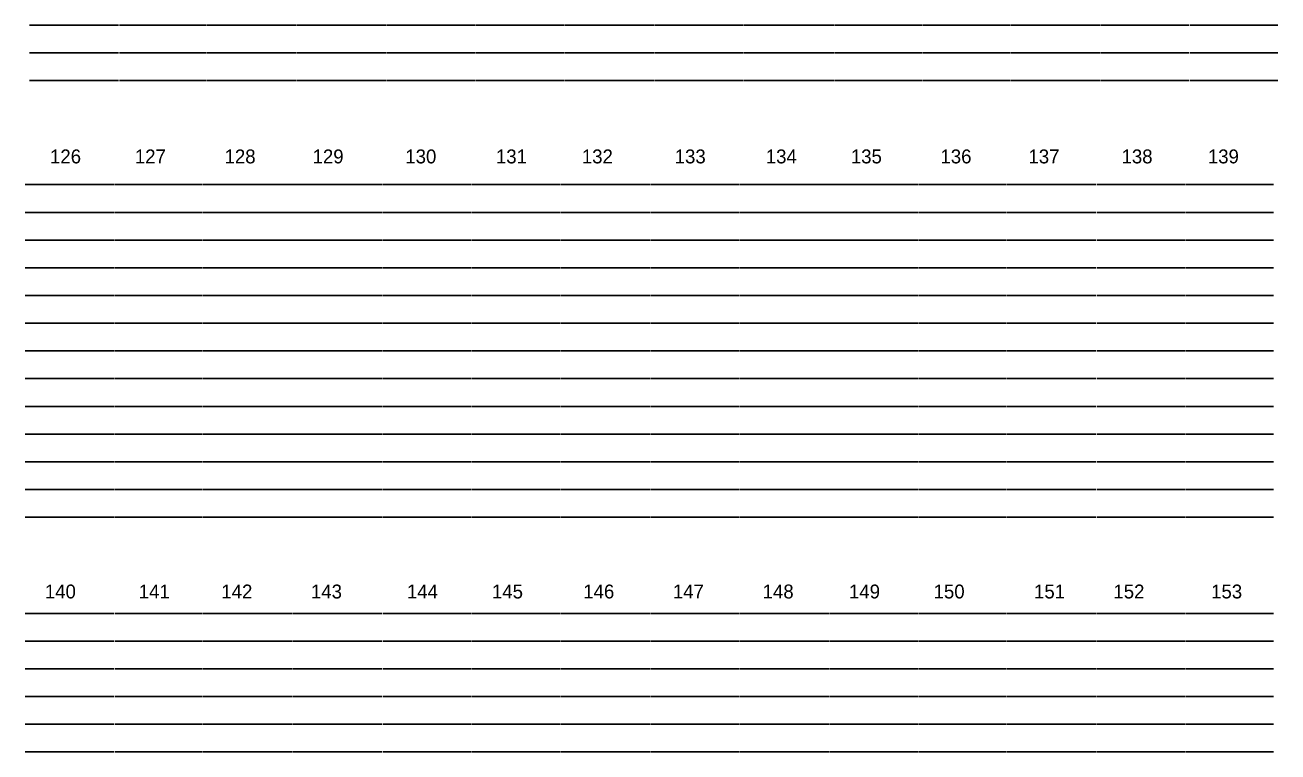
# Model space of a CAD drawing. Extents: x 11193 to 12507, y 10092 to 10555.
# Drawn here: x 11448.5 to 11644.1, y 10324.8 to 10438.4 of the extents above; entities that cross this region are included whole.
import ezdxf

# ---------------------------------------------------------------- set-up
doc = ezdxf.new("R2010")
doc.units = 0
doc.layers.add('Level 2', color=7, linetype='Continuous')

msp = doc.modelspace()

# ---------------------------------------------------------------- linework, layer by layer
at = {"layer": 'Level 2'}
for p, q in [((11449.15, 10438.4), (11463.08, 10438.4)), ((11463.2, 10438.4), (11476.76, 10438.4)), ((11476.87, 10438.4), (11490.84, 10438.4)), ((11490.96, 10438.4), (11504.92, 10438.4)), ((11505.04, 10438.4), (11518.81, 10438.4)), ((11518.92, 10438.4), (11532.69, 10438.4)), ((11532.79, 10438.4), (11546.77, 10438.4)), ((11546.87, 10438.4), (11560.65, 10438.4)), ((11560.75, 10438.4), (11574.74, 10438.4)), ((11574.84, 10438.4), (11588.61, 10438.4)), ((11588.71, 10438.4), (11602.29, 10438.4)), ((11602.39, 10438.4), (11616.37, 10438.4)), ((11616.47, 10438.4), (11630.25, 10438.4)), ((11630.36, 10438.4), (11644.09, 10438.4)), ((11449.15, 10434.07), (11463.08, 10434.07)), ((11463.2, 10434.07), (11476.76, 10434.07)), ((11476.87, 10434.07), (11490.84, 10434.07)), ((11490.96, 10434.07), (11504.92, 10434.07)), ((11505.04, 10434.07), (11518.81, 10434.07)), ((11518.92, 10434.07), (11532.69, 10434.07)), ((11532.79, 10434.07), (11546.77, 10434.07)), ((11546.87, 10434.07), (11560.65, 10434.07)), ((11560.75, 10434.07), (11574.74, 10434.07)), ((11574.84, 10434.07), (11588.61, 10434.07)), ((11588.71, 10434.07), (11602.29, 10434.07)), ((11602.39, 10434.07), (11616.37, 10434.07)), ((11616.47, 10434.07), (11630.25, 10434.07)), ((11630.36, 10434.07), (11644.09, 10434.07)), ((11449.15, 10429.74), (11463.08, 10429.74)), ((11463.2, 10429.74), (11476.76, 10429.74)), ((11476.87, 10429.74), (11490.84, 10429.74)), ((11490.96, 10429.74), (11504.92, 10429.74)), ((11505.04, 10429.74), (11518.81, 10429.74)), ((11518.92, 10429.74), (11532.69, 10429.74)), ((11532.79, 10429.74), (11546.77, 10429.74)), ((11546.87, 10429.74), (11560.65, 10429.74)), ((11560.75, 10429.74), (11574.74, 10429.74)), ((11574.84, 10429.74), (11588.61, 10429.74)), ((11588.71, 10429.74), (11602.29, 10429.74)), ((11602.39, 10429.74), (11616.37, 10429.74)), ((11616.47, 10429.74), (11630.25, 10429.74)), ((11630.36, 10429.74), (11644.09, 10429.74)), ((11448.48, 10413.46), (11462.4, 10413.46)), ((11462.5, 10413.46), (11476.08, 10413.46)), ((11476.18, 10413.46), (11490.16, 10413.46)), ((11490.26, 10413.46), (11504.24, 10413.46)), ((11504.35, 10413.46), (11518.12, 10413.46)), ((11518.23, 10413.46), (11532, 10413.46)), ((11532.11, 10413.46), (11546.08, 10413.46)), ((11546.19, 10413.46), (11559.97, 10413.46)), ((11560.08, 10413.46), (11574.05, 10413.46)), ((11574.15, 10413.46), (11587.93, 10413.46)), ((11588.04, 10413.46), (11601.6, 10413.46)), ((11601.71, 10413.46), (11615.68, 10413.46)), ((11615.79, 10413.46), (11629.57, 10413.46)), ((11629.68, 10413.46), (11643.42, 10413.46)), ((11448.48, 10409.13), (11462.4, 10409.13)), ((11462.5, 10409.13), (11476.08, 10409.13)), ((11476.18, 10409.13), (11490.16, 10409.13)), ((11490.26, 10409.13), (11504.24, 10409.13)), ((11504.35, 10409.13), (11518.12, 10409.13)), ((11518.23, 10409.13), (11532, 10409.13)), ((11532.11, 10409.13), (11546.08, 10409.13)), ((11546.19, 10409.13), (11559.97, 10409.13)), ((11560.08, 10409.13), (11574.05, 10409.13)), ((11574.15, 10409.13), (11587.93, 10409.13)), ((11588.04, 10409.13), (11601.6, 10409.13)), ((11601.71, 10409.13), (11615.68, 10409.13)), ((11615.79, 10409.13), (11629.57, 10409.13)), ((11629.68, 10409.13), (11643.42, 10409.13)), ((11448.48, 10404.8), (11462.4, 10404.8)), ((11462.5, 10404.8), (11476.08, 10404.8)), ((11476.18, 10404.8), (11490.16, 10404.8)), ((11490.26, 10404.8), (11504.24, 10404.8)), ((11504.35, 10404.8), (11518.12, 10404.8)), ((11518.23, 10404.8), (11532, 10404.8)), ((11532.11, 10404.8), (11546.08, 10404.8)), ((11546.19, 10404.8), (11559.97, 10404.8)), ((11560.08, 10404.8), (11574.05, 10404.8)), ((11574.15, 10404.8), (11587.93, 10404.8)), ((11588.04, 10404.8), (11601.6, 10404.8)), ((11601.71, 10404.8), (11615.68, 10404.8)), ((11615.79, 10404.8), (11629.57, 10404.8)), ((11629.68, 10404.8), (11643.42, 10404.8)), ((11448.48, 10400.47), (11462.4, 10400.47)), ((11462.5, 10400.47), (11476.08, 10400.47)), ((11476.18, 10400.47), (11490.16, 10400.47)), ((11490.26, 10400.47), (11504.24, 10400.47)), ((11504.35, 10400.47), (11518.12, 10400.47)), ((11518.23, 10400.47), (11532, 10400.47)), ((11532.11, 10400.47), (11546.08, 10400.47)), ((11546.19, 10400.47), (11559.97, 10400.47)), ((11560.08, 10400.47), (11574.05, 10400.47)), ((11574.15, 10400.47), (11587.93, 10400.47)), ((11588.04, 10400.47), (11601.6, 10400.47)), ((11601.71, 10400.47), (11615.68, 10400.47)), ((11615.79, 10400.47), (11629.57, 10400.47)), ((11629.68, 10400.47), (11643.42, 10400.47)), ((11448.48, 10396.14), (11462.4, 10396.14)), ((11462.5, 10396.14), (11476.08, 10396.14)), ((11476.18, 10396.14), (11490.16, 10396.14)), ((11490.26, 10396.14), (11504.24, 10396.14)), ((11504.35, 10396.14), (11518.12, 10396.14)), ((11518.23, 10396.14), (11532, 10396.14)), ((11532.11, 10396.14), (11546.08, 10396.14)), ((11546.19, 10396.14), (11559.97, 10396.14)), ((11560.08, 10396.14), (11574.05, 10396.14)), ((11574.15, 10396.14), (11587.93, 10396.14)), ((11588.04, 10396.14), (11601.6, 10396.14)), ((11601.71, 10396.14), (11615.68, 10396.14)), ((11615.79, 10396.14), (11629.57, 10396.14)), ((11629.68, 10396.14), (11643.42, 10396.14)), ((11448.48, 10391.8), (11462.4, 10391.8)), ((11462.5, 10391.8), (11476.08, 10391.8)), ((11476.18, 10391.8), (11490.16, 10391.8)), ((11490.26, 10391.8), (11504.24, 10391.8)), ((11504.35, 10391.8), (11518.12, 10391.8)), ((11518.23, 10391.8), (11532, 10391.8)), ((11532.11, 10391.8), (11546.08, 10391.8)), ((11546.19, 10391.8), (11559.97, 10391.8)), ((11560.08, 10391.8), (11574.05, 10391.8)), ((11574.15, 10391.8), (11587.93, 10391.8)), ((11588.04, 10391.8), (11601.6, 10391.8)), ((11601.71, 10391.8), (11615.68, 10391.8)), ((11615.79, 10391.8), (11629.57, 10391.8)), ((11629.68, 10391.8), (11643.42, 10391.8)), ((11448.48, 10387.47), (11462.4, 10387.47)), ((11462.5, 10387.47), (11476.08, 10387.47)), ((11476.18, 10387.47), (11490.16, 10387.47)), ((11490.26, 10387.47), (11504.24, 10387.47)), ((11504.35, 10387.47), (11518.12, 10387.47)), ((11518.23, 10387.47), (11532, 10387.47)), ((11532.11, 10387.47), (11546.08, 10387.47)), ((11546.19, 10387.47), (11559.97, 10387.47)), ((11560.08, 10387.47), (11574.05, 10387.47)), ((11574.15, 10387.47), (11587.93, 10387.47)), ((11588.04, 10387.47), (11601.6, 10387.47)), ((11601.71, 10387.47), (11615.68, 10387.47)), ((11615.79, 10387.47), (11629.57, 10387.47)), ((11629.68, 10387.47), (11643.42, 10387.47)), ((11448.48, 10383.14), (11462.4, 10383.14)), ((11462.5, 10383.14), (11476.08, 10383.14)), ((11476.18, 10383.14), (11490.16, 10383.14)), ((11490.26, 10383.14), (11504.24, 10383.14)), ((11504.35, 10383.14), (11518.12, 10383.14)), ((11518.23, 10383.14), (11532, 10383.14)), ((11532.11, 10383.14), (11546.08, 10383.14)), ((11546.19, 10383.14), (11559.97, 10383.14)), ((11560.08, 10383.14), (11574.05, 10383.14)), ((11574.15, 10383.14), (11587.93, 10383.14)), ((11588.04, 10383.14), (11601.6, 10383.14)), ((11601.71, 10383.14), (11615.68, 10383.14)), ((11615.79, 10383.14), (11629.57, 10383.14)), ((11629.68, 10383.14), (11643.42, 10383.14)), ((11448.48, 10378.81), (11462.4, 10378.81)), ((11462.5, 10378.81), (11476.08, 10378.81)), ((11476.18, 10378.81), (11490.16, 10378.81)), ((11490.26, 10378.81), (11504.24, 10378.81)), ((11504.35, 10378.81), (11518.12, 10378.81)), ((11518.23, 10378.81), (11532, 10378.81)), ((11532.11, 10378.81), (11546.08, 10378.81)), ((11546.19, 10378.81), (11559.97, 10378.81)), ((11560.08, 10378.81), (11574.05, 10378.81)), ((11574.15, 10378.81), (11587.93, 10378.81)), ((11588.04, 10378.81), (11601.6, 10378.81)), ((11601.71, 10378.81), (11615.68, 10378.81)), ((11615.79, 10378.81), (11629.57, 10378.81)), ((11629.68, 10378.81), (11643.42, 10378.81)), ((11448.48, 10374.48), (11462.4, 10374.48)), ((11462.5, 10374.48), (11476.08, 10374.48)), ((11476.18, 10374.48), (11490.16, 10374.48)), ((11490.26, 10374.48), (11504.24, 10374.48)), ((11504.35, 10374.48), (11518.12, 10374.48)), ((11518.23, 10374.48), (11532, 10374.48)), ((11532.11, 10374.48), (11546.08, 10374.48)), ((11546.19, 10374.48), (11559.97, 10374.48)), ((11560.08, 10374.48), (11574.05, 10374.48)), ((11574.15, 10374.48), (11587.93, 10374.48)), ((11588.04, 10374.48), (11601.6, 10374.48)), ((11601.71, 10374.48), (11615.68, 10374.48)), ((11615.79, 10374.48), (11629.57, 10374.48)), ((11629.68, 10374.48), (11643.42, 10374.48)), ((11448.48, 10370.14), (11462.4, 10370.14)), ((11462.5, 10370.14), (11476.08, 10370.14)), ((11476.18, 10370.14), (11490.16, 10370.14)), ((11490.26, 10370.14), (11504.24, 10370.14)), ((11504.35, 10370.14), (11518.12, 10370.14)), ((11518.23, 10370.14), (11532, 10370.14)), ((11532.11, 10370.14), (11546.08, 10370.14)), ((11546.19, 10370.14), (11559.97, 10370.14)), ((11560.08, 10370.14), (11574.05, 10370.14)), ((11574.15, 10370.14), (11587.93, 10370.14)), ((11588.04, 10370.14), (11601.6, 10370.14)), ((11601.71, 10370.14), (11615.68, 10370.14)), ((11615.79, 10370.14), (11629.57, 10370.14)), ((11629.68, 10370.14), (11643.42, 10370.14)), ((11448.48, 10365.81), (11462.4, 10365.81)), ((11462.5, 10365.81), (11476.08, 10365.81)), ((11476.18, 10365.81), (11490.16, 10365.81)), ((11490.26, 10365.81), (11504.24, 10365.81)), ((11504.35, 10365.81), (11518.12, 10365.81)), ((11518.23, 10365.81), (11532, 10365.81)), ((11532.11, 10365.81), (11546.08, 10365.81)), ((11546.19, 10365.81), (11559.97, 10365.81)), ((11560.08, 10365.81), (11574.05, 10365.81)), ((11574.15, 10365.81), (11587.93, 10365.81)), ((11588.04, 10365.81), (11601.6, 10365.81)), ((11601.71, 10365.81), (11615.68, 10365.81)), ((11615.79, 10365.81), (11629.57, 10365.81)), ((11629.68, 10365.81), (11643.42, 10365.81)), ((11448.48, 10361.48), (11462.4, 10361.48)), ((11462.5, 10361.48), (11476.08, 10361.48)), ((11476.18, 10361.48), (11490.16, 10361.48)), ((11490.26, 10361.48), (11504.24, 10361.48)), ((11504.35, 10361.48), (11518.12, 10361.48)), ((11518.23, 10361.48), (11532, 10361.48)), ((11532.11, 10361.48), (11546.08, 10361.48)), ((11546.19, 10361.48), (11559.97, 10361.48)), ((11560.08, 10361.48), (11574.05, 10361.48)), ((11574.15, 10361.48), (11587.93, 10361.48)), ((11588.04, 10361.48), (11601.6, 10361.48)), ((11601.71, 10361.48), (11615.68, 10361.48)), ((11615.79, 10361.48), (11629.57, 10361.48)), ((11629.68, 10361.48), (11643.42, 10361.48)), ((11448.48, 10346.46), (11462.41, 10346.46)), ((11462.53, 10346.46), (11476.09, 10346.46)), ((11476.2, 10346.46), (11490.17, 10346.46)), ((11490.29, 10346.46), (11504.25, 10346.46)), ((11504.37, 10346.46), (11518.14, 10346.46)), ((11518.25, 10346.46), (11532.02, 10346.46)), ((11532.12, 10346.46), (11546.1, 10346.46)), ((11546.2, 10346.46), (11559.98, 10346.46)), ((11560.08, 10346.46), (11574.07, 10346.46)), ((11574.17, 10346.46), (11587.94, 10346.46)), ((11588.04, 10346.46), (11601.62, 10346.46)), ((11601.72, 10346.46), (11615.7, 10346.46)), ((11615.8, 10346.46), (11629.58, 10346.46)), ((11629.69, 10346.46), (11643.42, 10346.46)), ((11448.48, 10342.13), (11462.41, 10342.13)), ((11462.53, 10342.13), (11476.09, 10342.13)), ((11476.2, 10342.13), (11490.17, 10342.13)), ((11490.29, 10342.13), (11504.25, 10342.13)), ((11504.37, 10342.13), (11518.14, 10342.13)), ((11518.25, 10342.13), (11532.02, 10342.13)), ((11532.12, 10342.13), (11546.1, 10342.13)), ((11546.2, 10342.13), (11559.98, 10342.13)), ((11560.08, 10342.13), (11574.07, 10342.13)), ((11574.17, 10342.13), (11587.94, 10342.13)), ((11588.04, 10342.13), (11601.62, 10342.13)), ((11601.72, 10342.13), (11615.7, 10342.13)), ((11615.8, 10342.13), (11629.58, 10342.13)), ((11629.69, 10342.13), (11643.42, 10342.13)), ((11448.48, 10337.79), (11462.41, 10337.79)), ((11462.53, 10337.79), (11476.09, 10337.79)), ((11476.2, 10337.79), (11490.17, 10337.79)), ((11490.29, 10337.79), (11504.25, 10337.79)), ((11504.37, 10337.79), (11518.14, 10337.79)), ((11518.25, 10337.79), (11532.02, 10337.79)), ((11532.12, 10337.79), (11546.1, 10337.79)), ((11546.2, 10337.79), (11559.98, 10337.79)), ((11560.08, 10337.79), (11574.07, 10337.79)), ((11574.17, 10337.79), (11587.94, 10337.79)), ((11588.04, 10337.79), (11601.62, 10337.79)), ((11601.72, 10337.79), (11615.7, 10337.79)), ((11615.8, 10337.79), (11629.58, 10337.79)), ((11629.69, 10337.79), (11643.42, 10337.79)), ((11448.48, 10333.46), (11462.41, 10333.46)), ((11462.53, 10333.46), (11476.09, 10333.46)), ((11476.2, 10333.46), (11490.17, 10333.46)), ((11490.29, 10333.46), (11504.25, 10333.46)), ((11504.37, 10333.46), (11518.14, 10333.46)), ((11518.25, 10333.46), (11532.02, 10333.46)), ((11532.12, 10333.46), (11546.1, 10333.46)), ((11546.2, 10333.46), (11559.98, 10333.46)), ((11560.08, 10333.46), (11574.07, 10333.46)), ((11574.17, 10333.46), (11587.94, 10333.46)), ((11588.04, 10333.46), (11601.62, 10333.46)), ((11601.72, 10333.46), (11615.7, 10333.46)), ((11615.8, 10333.46), (11629.58, 10333.46)), ((11629.69, 10333.46), (11643.42, 10333.46)), ((11448.48, 10329.13), (11462.41, 10329.13)), ((11462.53, 10329.13), (11476.09, 10329.13)), ((11476.2, 10329.13), (11490.17, 10329.13)), ((11490.29, 10329.13), (11504.25, 10329.13)), ((11504.37, 10329.13), (11518.14, 10329.13)), ((11518.25, 10329.13), (11532.02, 10329.13)), ((11532.12, 10329.13), (11546.1, 10329.13)), ((11546.2, 10329.13), (11559.98, 10329.13)), ((11560.08, 10329.13), (11574.07, 10329.13)), ((11574.17, 10329.13), (11587.94, 10329.13)), ((11588.04, 10329.13), (11601.62, 10329.13)), ((11601.72, 10329.13), (11615.7, 10329.13)), ((11615.8, 10329.13), (11629.58, 10329.13)), ((11629.69, 10329.13), (11643.42, 10329.13)), ((11448.48, 10324.8), (11462.41, 10324.8)), ((11462.53, 10324.8), (11476.09, 10324.8)), ((11476.2, 10324.8), (11490.17, 10324.8)), ((11490.29, 10324.8), (11504.25, 10324.8)), ((11504.37, 10324.8), (11518.14, 10324.8)), ((11518.25, 10324.8), (11532.02, 10324.8)), ((11532.12, 10324.8), (11546.1, 10324.8)), ((11546.2, 10324.8), (11559.98, 10324.8)), ((11560.08, 10324.8), (11574.07, 10324.8)), ((11574.17, 10324.8), (11587.94, 10324.8)), ((11588.04, 10324.8), (11601.62, 10324.8)), ((11601.72, 10324.8), (11615.7, 10324.8)), ((11615.8, 10324.8), (11629.58, 10324.8)), ((11629.69, 10324.8), (11643.42, 10324.8))]:
    msp.add_line(p, q, dxfattribs=at)

# ---------------------------------------------------------------- texts
for s, p in [('126', (11452.38, 10416.78)), ('127', (11465.62, 10416.78)), ('128', (11479.63, 10416.78)), ('129', (11493.37, 10416.78)), ('130', (11507.85, 10416.78)), ('131', (11522, 10416.78)), ('132', (11535.41, 10416.78)), ('133', (11549.91, 10416.78)), ('134', (11564.13, 10416.78)), ('135', (11577.41, 10416.78)), ('136', (11591.4, 10416.78)), ('137', (11605.14, 10416.78)), ('138', (11619.67, 10416.78)), ('139', (11633.15, 10416.78)), ('140', (11451.57, 10348.79)), ('141', (11466.23, 10348.79)), ('142', (11479.13, 10348.79)), ('143', (11493.12, 10348.79)), ('144', (11508.1, 10348.79)), ('145', (11521.38, 10348.79)), ('146', (11535.63, 10348.79)), ('147', (11549.62, 10348.79)), ('148', (11563.64, 10348.79)), ('149', (11577.12, 10348.79)), ('150', (11590.33, 10348.79)), ('151', (11606.01, 10348.79)), ('152', (11618.4, 10348.79)), ('153', (11633.66, 10348.79))]:
    msp.add_text(s, height=2.17, dxfattribs=at).set_placement(p)

doc.saveas('drawing.dxf')
